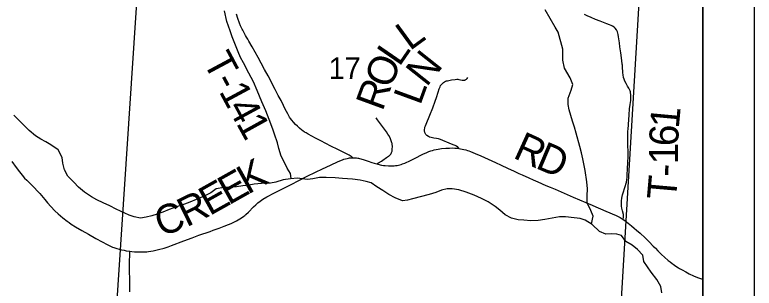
# Model space of a CAD drawing. Extents: x 0 to 34, y 0 to 22.
# Drawn here: x 29.474 to 30.917, y 19.446 to 19.979 of the extents above; entities that cross this region are included whole.
import ezdxf

# ---------------------------------------------------------------- set-up
doc = ezdxf.new("R2010")
doc.units = 0
for name, color, linetype in [('GM_X_Adjacent_County', 7, 'Continuous'), ('GM_X_County', 7, 'Continuous'), ('GM_X_County_Road', 7, 'Continuous'), ('GM_X_County_Road_Text', 7, 'Continuous'), ('GM_X_Minor_River', 7, 'Continuous'), ('GM_X_Section', 7, 'Continuous'), ('GM_X_Section_Text', 7, 'Continuous'), ('GM_X_Township', 7, 'Continuous'), ('GM_X_Township_Road', 7, 'Continuous'), ('GM_X_Township_Road_Text', 7, 'Continuous'), ('SH_Data', 7, 'Continuous')]:
    doc.layers.add(name, color=color, linetype=linetype)

msp = doc.modelspace()

# ---------------------------------------------------------------- linework, layer by layer
at = {"layer": 'GM_X_Adjacent_County'}
msp.add_lwpolyline([(28.5181, 14.1), (30.8167, 14.1), (30.8167, 20.9), (28.7526, 20.9)], dxfattribs=at)
at = {"layer": 'GM_X_County'}
msp.add_lwpolyline([(28.5181, 14.1), (30.8167, 14.1), (30.8167, 20.9), (28.7526, 20.9)], dxfattribs=at)
at = {"layer": 'GM_X_County_Road'}
for points in [[(30.1804, 19.6884), (30.1822, 19.6879), (30.1895, 19.6863), (30.1931, 19.6857), (30.1966, 19.6853), (30.2027, 19.6846), (30.2057, 19.6845), (30.2086, 19.6846), (30.2137, 19.6849), (30.2168, 19.6852), (30.2197, 19.6856), (30.2222, 19.6861), (30.2252, 19.6869), (30.2278, 19.6876), (30.2305, 19.6885), (30.2349, 19.6901), (30.2387, 19.6917), (30.2423, 19.6934), (30.254, 19.6992), (30.27, 19.7073), (30.2779, 19.7109), (30.2818, 19.7125), (30.2856, 19.7138), (30.289, 19.7149), (30.2924, 19.7158), (30.2958, 19.7166), (30.2997, 19.7173), (30.3064, 19.7183), (30.3149, 19.7191), (30.3217, 19.7195), (30.3276, 19.7196), (30.3321, 19.7195), (30.3348, 19.7193), (30.3373, 19.719), (30.3401, 19.7187), (30.3403, 19.7187)], [(30.3403, 19.7187), (30.3435, 19.7181), (30.3468, 19.7175), (30.35, 19.7167), (30.3536, 19.7158), (30.3569, 19.7148), (30.3595, 19.7139), (30.3627, 19.7128), (30.3719, 19.709), (30.3833, 19.7041), (30.4115, 19.691), (30.4228, 19.6858), (30.4351, 19.6802), (30.448, 19.6744), (30.4576, 19.67), (30.4641, 19.6671), (30.4769, 19.6612), (30.4852, 19.6575), (30.4942, 19.6535), (30.5103, 19.6466), (30.5183, 19.6432), (30.5281, 19.6391), (30.5635, 19.6239), (30.6007, 19.6078)], [(29.6983, 19.5182), (29.7019, 19.5177), (29.7071, 19.5172), (29.7118, 19.517), (29.7206, 19.5167), (29.7281, 19.517), (29.7316, 19.5172), (29.7349, 19.5176), (29.7389, 19.5181), (29.7436, 19.519), (29.749, 19.5202), (29.7539, 19.5214), (29.7653, 19.5245), (29.7732, 19.527), (29.7795, 19.5292), (29.8034, 19.5382), (29.8196, 19.5444), (29.833, 19.5494), (29.8547, 19.557), (29.8611, 19.5593), (29.8723, 19.5631), (29.8822, 19.5668), (29.8909, 19.5702), (29.896, 19.5725), (29.9022, 19.5754), (29.9061, 19.5774), (29.9099, 19.5795), (29.9129, 19.5813), (29.9158, 19.5832), (29.9204, 19.5864), (29.9225, 19.5881), (29.9248, 19.59), (29.9298, 19.5947), (29.9394, 19.6045), (29.9438, 19.6088), (29.9479, 19.6123), (29.9524, 19.6157), (29.958, 19.6195), (29.9654, 19.624), (29.9705, 19.627), (29.9751, 19.6295), (29.9894, 19.6368), (30.014, 19.6492), (30.0269, 19.6556), (30.0443, 19.6643), (30.0605, 19.6722), (30.0744, 19.679), (30.0896, 19.6862), (30.1048, 19.6931), (30.1129, 19.6964), (30.1159, 19.6975), (30.1188, 19.6984), (30.1221, 19.6993), (30.1246, 19.6998), (30.127, 19.7001), (30.1294, 19.7004), (30.1317, 19.7005), (30.1332, 19.7006)], [(30.1332, 19.7006), (30.1343, 19.7006), (30.1385, 19.7003), (30.1406, 19.7001), (30.1429, 19.6998), (30.1442, 19.6996), (30.1461, 19.6992), (30.1488, 19.6985), (30.1558, 19.6962), (30.1636, 19.6937), (30.1703, 19.6915), (30.1753, 19.6899), (30.1804, 19.6884)], [(29.4679, 19.6931), (29.4762, 19.6813), (29.4827, 19.6728), (29.4878, 19.6665), (29.4928, 19.6609), (29.4972, 19.6565), (29.507, 19.6469), (29.5123, 19.6417), (29.5174, 19.6363), (29.5223, 19.6308), (29.5322, 19.6188), (29.5374, 19.6126), (29.5442, 19.6053), (29.5521, 19.5973), (29.5585, 19.5914), (29.5674, 19.5836), (29.5757, 19.577), (29.58, 19.574), (29.5839, 19.5713), (29.5924, 19.5661), (29.6047, 19.5588), (29.6175, 19.5512), (29.6321, 19.5429), (29.6441, 19.5363), (29.6539, 19.5311), (29.6616, 19.5273), (29.6641, 19.5264), (29.6671, 19.5253), (29.6731, 19.5234), (29.6773, 19.5222), (29.6822, 19.5211), (29.6868, 19.52), (29.6913, 19.5192), (29.6983, 19.5182)], [(30.6007, 19.6078), (30.6017, 19.6074), (30.6268, 19.5966), (30.6472, 19.5876), (30.6509, 19.5859), (30.6549, 19.5837), (30.6607, 19.5802)], [(30.6607, 19.5802), (30.6607, 19.5802), (30.6641, 19.578), (30.6673, 19.5757), (30.6774, 19.5675), (30.6822, 19.5635), (30.6869, 19.5595), (30.694, 19.5534), (30.7036, 19.5446), (30.708, 19.5403), (30.7101, 19.5381), (30.7119, 19.5363), (30.7197, 19.5284), (30.7231, 19.5248), (30.724, 19.5239), (30.7288, 19.5191), (30.7358, 19.5121), (30.7418, 19.5066), (30.7488, 19.5004), (30.7527, 19.4973), (30.7567, 19.4943), (30.7582, 19.4932), (30.7639, 19.4893), (30.769, 19.4859), (30.7711, 19.4845), (30.7759, 19.4816), (30.783, 19.4777), (30.7897, 19.4742), (30.7982, 19.4703), (30.8063, 19.467), (30.8139, 19.4643), (30.8167, 19.4635)], [(29.6983, 19.4387), (29.698, 19.4572), (29.6976, 19.4861), (29.6978, 19.5015), (29.6979, 19.5077), (29.6983, 19.517), (29.6983, 19.5182)]]:
    msp.add_lwpolyline(points, dxfattribs=at)
at = {"layer": 'GM_X_Minor_River'}
for points in [[(30.0131, 19.6598), (30.0114, 19.6699), (30.0053, 19.6801), (29.9991, 19.6925), (29.9937, 19.7035), (29.9887, 19.7189), (29.9863, 19.7295), (29.9808, 19.7465), (29.9773, 19.7563), (29.97, 19.7752), (29.9634, 19.7922), (29.9556, 19.8096), (29.9467, 19.8315), (29.9398, 19.8485), (29.9305, 19.8658), (29.9197, 19.8854), (29.9143, 19.8963), (29.9097, 19.9069), (29.8981, 19.9367), (29.8942, 19.9481), (29.8876, 19.9666), (29.8828, 19.9874)], [(30.599, 19.5714), (30.6026, 19.5868), (30.5976, 19.5977), (30.5907, 19.6124), (30.5905, 19.6261), (30.5912, 19.6401), (30.5903, 19.6537), (30.5867, 19.6757), (30.5819, 19.6984), (30.5795, 19.7101), (30.5764, 19.7226), (30.5693, 19.7483), (30.5658, 19.7604), (30.5623, 19.7721), (30.5588, 19.783), (30.5557, 19.794), (30.5537, 19.8042), (30.5539, 19.8171), (30.5595, 19.8323), (30.5624, 19.8437), (30.5574, 19.8565), (30.5466, 19.875), (30.543, 19.8909), (30.5433, 19.9026), (30.5432, 19.9125), (30.5338, 19.9454), (30.5284, 19.9555), (30.5184, 19.9725), (30.5088, 19.9891)], [(30.1133, 19.6599), (30.0989, 19.6613), (30.0815, 19.6623), (30.0683, 19.6617), (30.0554, 19.6597), (30.0449, 19.6581), (30.0346, 19.6595), (30.0251, 19.6606), (30.0115, 19.6597), (29.9976, 19.6573), (29.9832, 19.6529), (29.973, 19.6509), (29.9552, 19.65), (29.9409, 19.6487), (29.9303, 19.6471), (29.9186, 19.6455), (29.9065, 19.6438), (29.8944, 19.6433), (29.8819, 19.6425), (29.8664, 19.6396), (29.8562, 19.6323), (29.8431, 19.6254), (29.8276, 19.6188), (29.8155, 19.6138), (29.805, 19.6099), (29.7891, 19.6048), (29.7752, 19.5997), (29.7623, 19.5947), (29.7518, 19.5908), (29.7408, 19.5872), (29.7299, 19.5845), (29.7193, 19.5829), (29.7064, 19.585), (29.6969, 19.5887), (29.6718, 19.6002), (29.6593, 19.6069), (29.6464, 19.6128), (29.6338, 19.6184), (29.6232, 19.624), (29.6098, 19.6333), (29.598, 19.6431), (29.5889, 19.6528), (29.5774, 19.6648), (29.5708, 19.6769), (29.5677, 19.6901), (29.5661, 19.7011), (29.558, 19.7158), (29.5443, 19.7259), (29.5344, 19.7319), (29.5245, 19.7367), (29.5138, 19.7434), (29.5016, 19.7535), (29.4879, 19.7674), (29.4718, 19.7836)], [(30.7365, 19.4373), (30.7345, 19.4494), (30.7264, 19.463), (30.7157, 19.4776), (30.7015, 19.4983), (30.6991, 19.5104), (30.6891, 19.5217), (30.6788, 19.5299), (30.6663, 19.537), (30.6579, 19.5491), (30.6484, 19.5512), (30.6389, 19.5523), (30.6272, 19.5514), (30.6146, 19.5566), (30.6005, 19.5705), (30.5868, 19.579), (30.5769, 19.582), (30.5656, 19.5834), (30.5485, 19.5851), (30.5364, 19.585), (30.5224, 19.5829), (30.5081, 19.5801), (30.4948, 19.5781), (30.4808, 19.5776), (30.4668, 19.5786), (30.4562, 19.5796), (30.4429, 19.5829), (30.4308, 19.5892), (30.4205, 19.5982), (30.4109, 19.6057), (30.3976, 19.6146), (30.3843, 19.6213), (30.3702, 19.6276), (30.3547, 19.6335), (30.3399, 19.6379), (30.3274, 19.6397), (30.3175, 19.64), (30.3066, 19.6376), (30.2953, 19.6329), (30.2824, 19.6286), (30.25, 19.6204), (30.2401, 19.618), (30.2303, 19.6168), (30.2159, 19.6223), (30.2037, 19.6286), (30.1919, 19.6368), (30.1805, 19.6439), (30.1691, 19.6514), (30.1596, 19.6543), (30.1474, 19.6569), (30.1326, 19.659), (30.1133, 19.6599)]]:
    msp.add_lwpolyline(points, dxfattribs=at)
at = {"layer": 'GM_X_Section'}
msp.add_line((30.8167, 19.2109), (30.8167, 20.2305), dxfattribs=at)
msp.add_lwpolyline([(30.7049, 20.2326), (30.6447, 19.2173), (29.6621, 19.2554), (29.7299, 20.2792)], close=True, dxfattribs=at)
msp.add_lwpolyline([(30.8167, 20.2305), (30.7049, 20.2326), (30.6447, 19.2173), (30.8167, 19.2109)], dxfattribs=at)
at = {"layer": 'GM_X_Township'}
msp.add_lwpolyline([(30.8167, 18.1651), (30.8167, 20.9), (28.7526, 20.9)], dxfattribs=at)
at = {"layer": 'GM_X_Township_Road'}
for points in [[(30.1332, 19.7006), (30.1327, 19.7011), (30.1316, 19.7021), (30.1298, 19.7033), (30.1261, 19.7053), (30.1038, 19.7165), (30.0904, 19.7234), (30.0709, 19.7334), (30.0605, 19.7389), (30.0465, 19.7465), (30.042, 19.749), (30.0392, 19.7507), (30.0361, 19.7529), (30.0337, 19.7546), (30.029, 19.7583), (30.0251, 19.7619), (30.0212, 19.7657), (30.0174, 19.7697), (30.0142, 19.7738), (30.0119, 19.777), (30.01, 19.7799), (30.0064, 19.7861), (30.0015, 19.7952), (29.9978, 19.8023), (29.9932, 19.812), (29.9879, 19.8223), (29.9819, 19.8338), (29.968, 19.8601), (29.961, 19.873), (29.9546, 19.8848), (29.9486, 19.896), (29.9425, 19.9066), (29.9368, 19.9169), (29.9306, 19.9278), (29.9283, 19.932), (29.9261, 19.9357), (29.9239, 19.9393), (29.9218, 19.9431), (29.9185, 19.9492), (29.9174, 19.9514), (29.9162, 19.9538), (29.9143, 19.9579), (29.9122, 19.9633), (29.9092, 19.972), (29.9064, 19.9804)], [(30.6607, 19.5802), (30.6607, 19.5807), (30.6614, 19.5848), (30.6614, 19.5869), (30.6613, 19.5896), (30.6594, 19.5971), (30.6584, 19.6019), (30.6578, 19.6058), (30.6574, 19.6111), (30.6578, 19.6168), (30.6584, 19.6218), (30.659, 19.6248), (30.6598, 19.628), (30.6605, 19.6304), (30.6647, 19.6445), (30.6667, 19.6511), (30.6672, 19.6532), (30.6682, 19.6583), (30.6686, 19.662), (30.669, 19.667), (30.6695, 19.6787), (30.6701, 19.691), (30.6704, 19.7028), (30.6704, 19.714), (30.6702, 19.7229), (30.6699, 19.7372), (30.6703, 19.7533), (30.6704, 19.7557), (30.6711, 19.7654), (30.6725, 19.784), (30.6736, 19.7958), (30.6748, 19.8044), (30.6757, 19.8124), (30.6761, 19.8181), (30.676, 19.8216), (30.6758, 19.8239), (30.6754, 19.8271), (30.675, 19.829), (30.6743, 19.8313), (30.6735, 19.8334), (30.6717, 19.8366), (30.6695, 19.8403), (30.6667, 19.8451), (30.6643, 19.8501), (30.6629, 19.8536), (30.6619, 19.8571), (30.6609, 19.862), (30.6604, 19.8663), (30.6597, 19.8785), (30.6595, 19.8814), (30.6593, 19.8831), (30.6584, 19.8902), (30.6562, 19.9055), (30.6546, 19.9171), (30.6535, 19.9246), (30.652, 19.9364), (30.6513, 19.941), (30.6499, 19.946), (30.6477, 19.9501), (30.6453, 19.9532), (30.6431, 19.9552), (30.6403, 19.957), (30.6373, 19.9586), (30.6342, 19.9601), (30.6292, 19.9619), (30.616, 19.9668), (30.607, 19.9704), (30.5988, 19.9739), (30.5907, 19.9775), (30.5852, 19.9802)], [(30.3403, 19.7187), (30.34, 19.7191), (30.3393, 19.7202), (30.3381, 19.7214), (30.3356, 19.723), (30.3328, 19.7244), (30.3292, 19.726), (30.3211, 19.7291), (30.3088, 19.7343), (30.3042, 19.7361), (30.3003, 19.7373), (30.2969, 19.7381), (30.2913, 19.739), (30.286, 19.7399), (30.2833, 19.7408), (30.2808, 19.7421), (30.2779, 19.7439), (30.2759, 19.7461), (30.275, 19.7474), (30.2744, 19.7487), (30.274, 19.7497), (30.2735, 19.753), (30.2734, 19.754), (30.2734, 19.7555), (30.2736, 19.7581), (30.2741, 19.7603), (30.2749, 19.7627), (30.2763, 19.766), (30.2838, 19.7839), (30.2893, 19.7977), (30.2942, 19.811), (30.2966, 19.818), (30.2998, 19.8287), (30.3018, 19.8351), (30.3035, 19.8391), (30.3047, 19.8412), (30.3065, 19.8437), (30.3089, 19.8463), (30.3105, 19.8475), (30.3124, 19.8488), (30.3142, 19.8498), (30.3162, 19.8503), (30.3181, 19.8508), (30.3207, 19.8513), (30.3261, 19.8523), (30.333, 19.8534), (30.3363, 19.8537), (30.3383, 19.8536), (30.3403, 19.8533), (30.3438, 19.8523), (30.3469, 19.8518), (30.3487, 19.8517), (30.35, 19.8517), (30.3512, 19.8518), (30.3518, 19.852), (30.3526, 19.8523), (30.3531, 19.8525), (30.354, 19.853), (30.3551, 19.8539), (30.3564, 19.8553), (30.3576, 19.8568)], [(30.1804, 19.6884), (30.1835, 19.6904), (30.189, 19.6938), (30.1919, 19.696), (30.1992, 19.7008), (30.203, 19.7035), (30.2041, 19.7043), (30.2053, 19.7053), (30.206, 19.706), (30.2066, 19.7067), (30.2074, 19.7078), (30.208, 19.7088), (30.2088, 19.7105), (30.2093, 19.7119), (30.2098, 19.7137), (30.2102, 19.716), (30.2104, 19.7186), (30.2106, 19.7211), (30.2106, 19.7236), (30.2104, 19.7251), (30.2102, 19.7268), (30.21, 19.7282), (30.2096, 19.7298), (30.2091, 19.7317), (30.2084, 19.7338), (30.2077, 19.7358), (30.207, 19.7375), (30.2059, 19.7397), (30.2034, 19.744), (30.2019, 19.7464), (30.1988, 19.7508), (30.1871, 19.767), (30.1816, 19.7748), (30.1788, 19.7787)]]:
    msp.add_lwpolyline(points, dxfattribs=at)
at = {"layer": 'SH_Data'}
for points in [[(23.9167, 21), (30.9167, 21), (30.9167, 14), (23.9167, 14)], [(24.0167, 20.9), (30.8167, 20.9), (30.8167, 14.1), (24.0167, 14.1)]]:
    msp.add_lwpolyline(points, close=True, dxfattribs=at)

# ---------------------------------------------------------------- texts
at = {"layer": 'GM_X_County_Road_Text'}
for s, rotation, p in [('R', 335.5334, (30.444, 19.7012)), ('D', 336.8767, (30.4878, 19.6812)), ('K', 29.2908, (29.9281, 19.6281)), ('E', 29.2822, (29.891, 19.6073)), ('E', 29.2068, (29.8538, 19.5865)), ('R', 25.9827, (29.8088, 19.5645)), ('C', 20.1175, (29.7591, 19.5459))]:
    msp.add_text(s, height=0.0568, rotation=rotation, dxfattribs=at).set_placement(p)
at = {"layer": 'GM_X_Section_Text'}
msp.add_text('17', height=0.04186, rotation=0, dxfattribs=at).set_placement((30.0863, 19.8544))
at = {"layer": 'GM_X_Township_Road_Text'}
for s, rotation, p in [('L', 36.125, (30.2445, 19.9081)), ('L', 55.4826, (30.224, 19.8767)), ('T', 298.25, (29.84, 19.8881)), ('N', 51.5882, (30.2771, 19.8371)), ('O', 68.181, (30.2069, 19.8332)), ('-', 298.2595, (29.8602, 19.8506)), ('1', 298.2985, (29.8712, 19.83)), ('R', 69.9035, (30.1911, 19.7898)), ('L', 69.9114, (30.2648, 19.8013)), ('4', 298.4391, (29.8879, 19.7991)), ('1', 298.893, (29.9048, 19.7679)), ('1', 84.7943, (30.7694, 19.7565)), ('6', 88.0898, (30.7683, 19.7223)), ('1', 89.9525, (30.7682, 19.6878)), ('-', 88.4262, (30.7676, 19.6629)), ('T', 85.0054, (30.7637, 19.6168))]:
    msp.add_text(s, height=0.0568, rotation=rotation, dxfattribs=at).set_placement(p)

doc.saveas('drawing.dxf')
